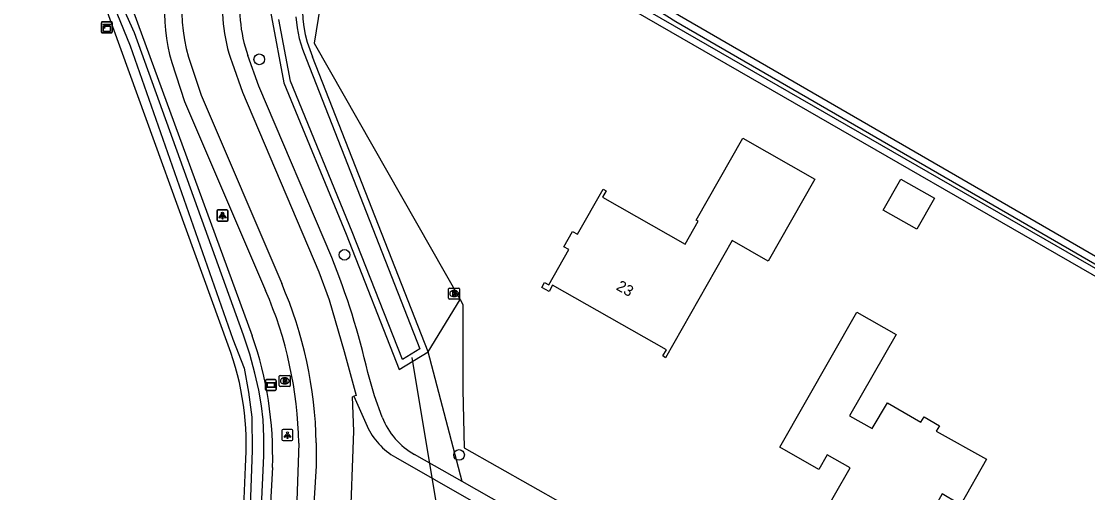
# Model space of a CAD drawing. Extents: x 156502 to 159074, y 384229 to 386094.
# Drawn here: x 157008.2 to 157105.6, y 385784.4 to 385827.5 of the extents above; entities that cross this region are included whole.
import ezdxf

# ---------------------------------------------------------------- set-up
doc = ezdxf.new("R2010")
doc.units = 0
for name, color, linetype in [('IMGEO_Berm_halfverhard', 7, 'Continuous'), ('IMGEO_Boom', 7, 'Continuous'), ('IMGEO_Brandkraan', 7, 'Continuous'), ('IMGEO_Duiker', 7, 'Continuous'), ('IMGEO_Erf', 7, 'Continuous'), ('IMGEO_Groenvoorziening', 7, 'Continuous'), ('IMGEO_Hek', 7, 'Continuous'), ('IMGEO_Kast', 7, 'Continuous'), ('IMGEO_Lichtpunt', 7, 'Continuous'), ('IMGEO_Loofbos', 7, 'Continuous'), ('IMGEO_Pand', 7, 'Continuous'), ('IMGEO_Pand_nummerreeks', 7, 'Continuous'), ('IMGEO_Rijbaan_lokaal_gesloten', 7, 'Continuous'), ('IMGEO_Rijbaan_lokaal_halfverhard', 7, 'Continuous'), ('IMGEO_Rioolput', 7, 'Continuous'), ('IMGEO_Verklikker', 7, 'Continuous'), ('IMGEO_Waterloop', 7, 'Continuous')]:
    doc.layers.add(name, color=color, linetype=linetype)

msp = doc.modelspace()

# ---------------------------------------------------------------- linework, layer by layer
at = {"layer": 'IMGEO_Berm_halfverhard'}
for points in [[(157021.98, 385823.692), (157023.16, 385820.139), (157030.552, 385802.892)], [(157033.583, 385788.947), (157033.399, 385783.694), (157031.512, 385744.51)]]:
    msp.add_lwpolyline(points, dxfattribs=at)
for centre, radius, start, end in [((157039.111, 385828.542), 17.804, 157.16468, 195.80884), ((156996.795, 385788.253), 36.795, 1.08108, 23.44438)]:
    msp.add_arc(centre, radius, start, end, dxfattribs=at)
at = {"layer": 'IMGEO_Boom'}
for centre in [(157029.976, 385823.992), (157037.758, 385806.141), (157048.22, 385787.874)]:
    msp.add_circle(centre, 0.489, dxfattribs=at)
at = {"layer": 'IMGEO_Brandkraan'}
for p, q in [((157031.804, 385794.205), (157031.804, 385795.057)), ((157031.879, 385795.131), (157032.731, 385795.131)), ((157032.292, 385794.911), (157032.317, 385794.911)), ((157032.805, 385795.057), (157032.805, 385794.205)), ((157032.731, 385794.131), (157031.879, 385794.131)), ((157032.315, 385794.351), (157032.29, 385794.351))]:
    msp.add_line(p, q, dxfattribs=at)
for points in [[(157031.804, 385794.205), (157031.804, 385795.057)], [(157031.879, 385795.131), (157032.731, 385795.131)], [(157032.152, 385794.831), (157032.152, 385794.431), (157032.365, 385794.431)], [(157032.383, 385794.831), (157032.152, 385794.831)], [(157032.805, 385795.057), (157032.805, 385794.205)], [(157032.731, 385794.131), (157031.879, 385794.131)], [(157032.331, 385794.75), (157032.277, 385794.75), (157032.277, 385794.674)], [(157032.277, 385794.674), (157032.33, 385794.674)], [(157032.339, 385794.598), (157032.277, 385794.598), (157032.277, 385794.517)], [(157032.277, 385794.517), (157032.339, 385794.517)]]:
    msp.add_lwpolyline(points, dxfattribs=at)
for centre, radius, start, end in [((157031.881, 385795.055), 0.0765, 91.55205, 178.44795), ((157031.881, 385795.055), 0.0765, 91.55205, 178.44795), ((157032.387, 385794.686), 0.145, 59.4692, 91.53667), ((157032.412, 385794.733), 0.0922, 285.51372, 58.15012), ((157032.729, 385795.055), 0.0765, 1.55205, 88.44795), ((157032.729, 385795.055), 0.0765, 1.55205, 88.44795), ((157031.881, 385794.207), 0.0765, 181.55205, 268.44795), ((157031.881, 385794.207), 0.0765, 181.55205, 268.44795), ((157032.332, 385794.712), 0.0379, 267.82845, 90.93552), ((157032.34, 385794.557), 0.0404, 269.87594, 90.50774), ((157032.371, 385794.682), 0.251, 268.66757, 293.53466), ((157032.417, 385794.541), 0.105, 301.31148, 78.98903), ((157032.729, 385794.207), 0.0765, 271.55205, 358.44795), ((157032.729, 385794.207), 0.0765, 271.55205, 358.44795)]:
    msp.add_arc(centre, radius, start, end, dxfattribs=at)
for centre, major_axis, ratio, start_param, end_param in [((157032.291, 385794.631), (-0.387, 0.002), 0.722429, 4.712389, 7.853982), ((157032.316, 385794.631), (-0.39, 0.002), 0.717154, 1.570796, 4.712389)]:
    msp.add_ellipse(centre, major_axis=major_axis, ratio=ratio, start_param=start_param, end_param=end_param, dxfattribs=at)
at = {"layer": 'IMGEO_Duiker'}
msp.add_lwpolyline([(157047.357, 385776.176), (157047.216, 385777.024), (157043.935, 385796.78)], dxfattribs=at)
at = {"layer": 'IMGEO_Erf'}
msp.add_lwpolyline([(157069.688, 385879.771), (157062.244, 385869.451), (157047.224, 385849.55), (157042.786, 385843.67), (157065.314, 385829.887), (157068.346, 385827.983), (157173.435, 385767.228), (157172.677, 385766.006), (157064.372, 385828.327), (157041.356, 385841.775), (157036.588, 385835.458)], dxfattribs=at)
at = {"layer": 'IMGEO_Groenvoorziening'}
for points in [[(157076.448, 385893.546), (157049.627, 385858.357), (157033.907, 385837.957), (157030.83, 385829.194), (157031.084, 385827.859), (157032.23, 385821.835), (157037.896, 385808.02), (157042.738, 385795.688), (157045.399, 385797.293)], [(157015.352, 385835.3), (157016.015, 385834.166), (157020.718, 385833.042), (157020.555, 385832.399), (157020.295, 385831.377), (157019.932, 385829.949), (157017.732, 385830.418), (157029.334, 385798.749)], [(157036.588, 385835.458), (157034.974, 385825.476), (157048.314, 385802.061)], [(157045.399, 385797.293), (157034.848, 385824.224)], [(157045.399, 385797.293), (157048.314, 385802.061)], [(157048.314, 385802.061), (157048.565, 385801.621), (157048.579, 385793.832), (157048.701, 385788.533), (157057.714, 385783.415)], [(157048.506, 385785.444), (157045.399, 385797.293)], [(157031.189, 385786.741), (157030.037, 385766.175), (157029.325, 385750), (157029.3, 385749.437)]]:
    msp.add_lwpolyline(points, dxfattribs=at)
for centre, radius, start, end in [((157044.63, 385828.574), 10.705, 143.35, 203.97313), ((156997.678, 385787.711), 33.525, 358.34127, 19.22204)]:
    msp.add_arc(centre, radius, start, end, dxfattribs=at)
at = {"layer": 'IMGEO_Hek'}
for points in [[(157036.588, 385835.458), (157034.974, 385825.476), (157048.314, 385802.061)], [(157048.314, 385802.061), (157048.565, 385801.621), (157048.579, 385793.832), (157048.701, 385788.533), (157057.714, 385783.415)]]:
    msp.add_lwpolyline(points, dxfattribs=at)
at = {"layer": 'IMGEO_Kast'}
for p, q in [((157015.553, 385826.485), (157015.553, 385827.326)), ((157015.553, 385827.326), (157015.553, 385826.485)), ((157015.628, 385827.41), (157016.469, 385827.41)), ((157016.469, 385827.41), (157015.628, 385827.41)), ((157016.553, 385827.335), (157016.553, 385826.494)), ((157016.553, 385826.494), (157016.553, 385827.335)), ((157016.478, 385826.41), (157015.637, 385826.41)), ((157015.637, 385826.41), (157016.478, 385826.41))]:
    msp.add_line(p, q, dxfattribs=at)
for points in [[(157015.748, 385827.2), (157016.348, 385827.2), (157016.348, 385827.115), (157015.748, 385827.115), (157015.748, 385827.2)], [(157015.748, 385827.025), (157016.348, 385827.025), (157016.348, 385826.536), (157015.748, 385826.536), (157015.748, 385827.025)]]:
    msp.add_lwpolyline(points, dxfattribs=at)
msp.add_circle((157015.832, 385826.874), 0.0377, dxfattribs=at)
for centre, start, end in [((157015.631, 385827.332), 92.4484, 184.28452), ((157015.631, 385827.332), 92.4484, 184.28452), ((157016.475, 385827.332), 2.4484, 94.28452), ((157016.475, 385827.332), 2.4484, 94.28452), ((157015.631, 385826.488), 182.4484, 274.28452), ((157015.631, 385826.488), 182.4484, 274.28452), ((157016.475, 385826.488), 272.4484, 4.28452), ((157016.475, 385826.488), 272.4484, 4.28452)]:
    msp.add_arc(centre, 0.0779, start, end, dxfattribs=at)
at = {"layer": 'IMGEO_Lichtpunt'}
for p, q in [((157026.111, 385810.147), (157026.111, 385809.34)), ((157026.111, 385810.147), (157026.111, 385809.34)), ((157026.126, 385810.12), (157026.126, 385809.313)), ((157026.126, 385810.12), (157026.126, 385809.313)), ((157027.013, 385810.242), (157026.205, 385810.242)), ((157027.013, 385810.242), (157026.205, 385810.242)), ((157027.028, 385810.215), (157026.22, 385810.215)), ((157027.028, 385810.215), (157026.22, 385810.215)), ((157027.107, 385809.34), (157027.107, 385810.147)), ((157027.107, 385809.34), (157027.107, 385810.147)), ((157027.122, 385809.313), (157027.122, 385810.12)), ((157027.122, 385809.313), (157027.122, 385810.12)), ((157026.205, 385809.246), (157027.013, 385809.246)), ((157026.205, 385809.246), (157027.013, 385809.246)), ((157026.22, 385809.219), (157027.028, 385809.219)), ((157026.22, 385809.219), (157027.028, 385809.219)), ((157032.05, 385790.09), (157032.05, 385789.283)), ((157032.05, 385790.09), (157032.05, 385789.283)), ((157032.952, 385790.185), (157032.144, 385790.185)), ((157032.952, 385790.185), (157032.144, 385790.185)), ((157033.046, 385789.283), (157033.046, 385790.09)), ((157033.046, 385789.283), (157033.046, 385790.09)), ((157032.144, 385789.189), (157032.952, 385789.189)), ((157032.144, 385789.189), (157032.952, 385789.189))]:
    msp.add_line(p, q, dxfattribs=at)
for points in [[(157026.485, 385809.811), (157026.524, 385809.783), (157026.336, 385809.521), (157026.298, 385809.548), (157026.485, 385809.811)], [(157026.5, 385809.784), (157026.539, 385809.756), (157026.351, 385809.494), (157026.313, 385809.521), (157026.5, 385809.784)], [(157026.587, 385809.763), (157026.634, 385809.763), (157026.634, 385809.441), (157026.587, 385809.441), (157026.587, 385809.763)], [(157026.602, 385809.736), (157026.649, 385809.736), (157026.649, 385809.414), (157026.602, 385809.414), (157026.602, 385809.736)], [(157026.697, 385809.783), (157026.735, 385809.81), (157026.922, 385809.548), (157026.883, 385809.52), (157026.697, 385809.783)], [(157026.712, 385809.756), (157026.75, 385809.783), (157026.937, 385809.521), (157026.898, 385809.493), (157026.712, 385809.756)], [(157032.424, 385789.754), (157032.463, 385789.726), (157032.275, 385789.464), (157032.237, 385789.491), (157032.424, 385789.754)], [(157032.526, 385789.706), (157032.573, 385789.706), (157032.573, 385789.384), (157032.526, 385789.384), (157032.526, 385789.706)], [(157032.636, 385789.726), (157032.674, 385789.753), (157032.861, 385789.491), (157032.822, 385789.463), (157032.636, 385789.726)]]:
    msp.add_lwpolyline(points, dxfattribs=at)
for centre in [(157026.61, 385809.945), (157026.625, 385809.918), (157032.549, 385789.888)]:
    msp.add_circle(centre, 0.0994, dxfattribs=at)
for centre, start, end in [((157026.205, 385810.147), 90, 180), ((157026.205, 385810.147), 90, 180), ((157026.22, 385810.12), 90, 180), ((157026.22, 385810.12), 90, 180), ((157027.013, 385810.147), 0, 90), ((157027.013, 385810.147), 0, 90), ((157027.028, 385810.12), 0, 90), ((157027.028, 385810.12), 0, 90), ((157026.205, 385809.34), 180, 270), ((157026.205, 385809.34), 180, 270), ((157026.22, 385809.313), 180, 270), ((157026.22, 385809.313), 180, 270), ((157027.013, 385809.34), 270, 0), ((157027.013, 385809.34), 270, 360), ((157027.028, 385809.313), 270, 0), ((157027.028, 385809.313), 270, 360), ((157032.144, 385790.09), 90, 180), ((157032.144, 385790.09), 90, 180), ((157032.952, 385790.09), 0, 90), ((157032.952, 385790.09), 0, 90), ((157032.144, 385789.283), 180, 270), ((157032.144, 385789.283), 180, 270), ((157032.952, 385789.283), 270, 0), ((157032.952, 385789.283), 270, 360)]:
    msp.add_arc(centre, 0.0946, start, end, dxfattribs=at)
at = {"layer": 'IMGEO_Loofbos'}
for points in [[(157027.141, 385797.89), (157015.854, 385829.061), (157010.805, 385836.629), (157000, 385855.161), (156976.182, 385896.012), (156952.047, 385938.123)], [(157027.243, 385749.848), (157027.249, 385750), (157027.878, 385766.343), (157028.705, 385786.777)]]:
    msp.add_lwpolyline(points, dxfattribs=at)
msp.add_arc((157003.007, 385788.827), 25.78, 355.43934, 20.5826, dxfattribs=at)
at = {"layer": 'IMGEO_Pand'}
for points in [[(157067.08, 385796.742), (157066.82, 385796.909), (157067.171, 385797.456), (157056.763, 385803.368), (157056.438, 385802.793), (157055.779, 385803.165), (157056.02, 385803.617), (157056.419, 385803.418), (157058.233, 385806.623), (157057.796, 385806.877), (157058.566, 385808.281), (157059.03, 385808.027), (157061.37, 385812.141), (157061.645, 385811.981), (157061.316, 385811.411), (157068.883, 385807.115), (157070.049, 385809.211), (157069.866, 385809.315), (157074.122, 385816.781), (157080.705, 385813.039), (157076.458, 385805.561), (157073.154, 385807.438), (157067.08, 385796.742)], [(157090.018, 385808.489), (157086.958, 385810.227), (157088.567, 385813.06), (157091.627, 385811.322), (157090.018, 385808.489)], [(157094.034, 385783.344), (157093.774, 385783.484), (157092.329, 385784.314), (157091.181, 385782.261), (157091.819, 385781.904), (157091.56, 385781.44), (157089.098, 385777.114), (157081.073, 385781.715), (157083.929, 385786.699), (157081.847, 385787.885), (157081.084, 385786.547), (157077.502, 385788.588), (157084.548, 385800.906), (157088.147, 385798.874), (157083.885, 385791.439), (157085.956, 385790.275), (157087.339, 385792.644), (157090.403, 385790.86), (157090.692, 385791.357), (157092.087, 385790.545), (157091.801, 385790.041), (157096.381, 385787.475), (157094.034, 385783.344)]]:
    msp.add_lwpolyline(points, dxfattribs=at)
at = {"layer": 'IMGEO_Rijbaan_lokaal_gesloten'}
for points in [[(157023.499, 385824.197), (157024.658, 385820.707), (157032.023, 385803.522)], [(157027.488, 385823.674), (157028.432, 385820.994), (157035.414, 385804.593), (157036.361, 385802.028), (157037.739, 385797.316), (157038.81, 385793.315), (157038.604, 385793.23)], [(157038.321, 385778.978), (157038.272, 385780.907), (157038.618, 385790.04), (157038.48, 385793.19), (157038.604, 385793.23)], [(157038.604, 385793.23), (157039.825, 385790.502)], [(157035.183, 385788.978), (157035.156, 385786.878), (157034.792, 385780.921), (157034.276, 385768.562), (157033.061, 385744.424)], [(157042.417, 385787.656), (157155.604, 385722.866)]]:
    msp.add_lwpolyline(points, dxfattribs=at)
for centre, radius, start, end in [((157039.128, 385828.54), 16.221, 149.95096, 195.52867), ((157041.52, 385828.676), 14.897, 171.39314, 199.61838), ((156996.765, 385788.246), 38.425, 1.09141, 23.42506), ((157045.486, 385793.055), 6.21, 204.27048, 240.38102)]:
    msp.add_arc(centre, radius, start, end, dxfattribs=at)
at = {"layer": 'IMGEO_Rijbaan_lokaal_halfverhard'}
for points in [[(157036.595, 385805.9), (157029.935, 385821.546), (157028.928, 385824.341)], [(157041.212, 385791.315), (157040.509, 385793.275), (157039.878, 385795.397)], [(157048.506, 385785.444), (157044.158, 385787.921)], [(157055.407, 385781.512), (157048.506, 385785.444)]]:
    msp.add_lwpolyline(points, dxfattribs=at)
for centre, radius, start, end in [((157041.034, 385828.611), 12.837, 169.82625, 199.42679), ((156974.097, 385780.6), 67.424, 12.67731, 22.03881), ((157047.365, 385793.68), 6.592, 201.02754, 240.88857)]:
    msp.add_arc(centre, radius, start, end, dxfattribs=at)
at = {"layer": 'IMGEO_Rioolput'}
for p, q in [((157047.271, 385802.178), (157047.271, 385803.03)), ((157047.346, 385803.104), (157048.198, 385803.104)), ((157047.759, 385802.884), (157047.784, 385802.884)), ((157048.272, 385803.03), (157048.272, 385802.178)), ((157048.198, 385802.104), (157047.346, 385802.104)), ((157047.782, 385802.324), (157047.757, 385802.324))]:
    msp.add_line(p, q, dxfattribs=at)
for points in [[(157047.271, 385802.178), (157047.271, 385803.03)], [(157047.346, 385803.104), (157048.198, 385803.104)], [(157047.86, 385802.802), (157047.608, 385802.804), (157047.608, 385802.404)], [(157047.786, 385802.723), (157047.732, 385802.723), (157047.732, 385802.642)], [(157047.732, 385802.642), (157047.784, 385802.642)], [(157048.272, 385803.03), (157048.272, 385802.178)], [(157048.198, 385802.104), (157047.346, 385802.104)], [(157047.608, 385802.404), (157047.732, 385802.404), (157047.732, 385802.566), (157047.743, 385802.566)], [(157047.79, 385802.537), (157047.861, 385802.404), (157048.001, 385802.404), (157047.936, 385802.53)]]:
    msp.add_lwpolyline(points, dxfattribs=at)
for centre, radius, start, end in [((157047.348, 385803.028), 0.0765, 91.55205, 178.44795), ((157047.348, 385803.028), 0.0765, 91.55205, 178.44795), ((157047.768, 385802.831), 0.19, 274.7715, 282.96867), ((157047.792, 385802.627), 0.0964, 77.00612, 93.18647), ((157047.806, 385802.684), 0.0378, 276.66336, 79.67722), ((157047.859, 385802.692), 0.109, 350.36119, 89.41601), ((157047.857, 385802.692), 0.112, 277.58423, 350.98172), ((157047.841, 385802.477), 0.108, 29.51342, 73.79051), ((157048.196, 385803.028), 0.0765, 1.55205, 88.44795), ((157048.196, 385803.028), 0.0765, 1.55205, 88.44795), ((157047.348, 385802.18), 0.0765, 181.55205, 268.44795), ((157047.348, 385802.18), 0.0765, 181.55205, 268.44795), ((157047.742, 385802.513), 0.0533, 26.02933, 88.69889), ((157048.196, 385802.18), 0.0765, 271.55205, 358.44795), ((157048.196, 385802.18), 0.0765, 271.55205, 358.44795)]:
    msp.add_arc(centre, radius, start, end, dxfattribs=at)
for centre, major_axis, ratio, start_param, end_param in [((157047.758, 385802.604), (-0.387, 0.002), 0.722429, 4.712389, 7.853982), ((157047.783, 385802.604), (-0.39, 0.002), 0.717154, 1.570796, 4.712389)]:
    msp.add_ellipse(centre, major_axis=major_axis, ratio=ratio, start_param=start_param, end_param=end_param, dxfattribs=at)
at = {"layer": 'IMGEO_Verklikker'}
for p, q in [((157030.538, 385793.848), (157030.538, 385794.648)), ((157030.538, 385794.648), (157030.538, 385793.848)), ((157030.638, 385794.748), (157031.428, 385794.748)), ((157031.428, 385794.748), (157030.638, 385794.748)), ((157031.528, 385794.648), (157031.528, 385793.848)), ((157031.528, 385793.848), (157031.528, 385794.648)), ((157031.428, 385793.748), (157030.638, 385793.748)), ((157030.638, 385793.748), (157031.428, 385793.748))]:
    msp.add_line(p, q, dxfattribs=at)
for points in [[(157030.639, 385794.48), (157031.427, 385794.48), (157031.427, 385794.016), (157030.639, 385794.016), (157030.639, 385794.48)], [(157030.704, 385794.415), (157030.704, 385794.081), (157031.362, 385794.081), (157031.362, 385794.415), (157030.704, 385794.415)]]:
    msp.add_lwpolyline(points, dxfattribs=at)
for centre, start, end in [((157030.638, 385794.648), 90, 180), ((157030.638, 385794.648), 90, 180), ((157030.638, 385793.848), 180, 270), ((157030.638, 385793.848), 180, 270), ((157031.428, 385794.648), 0, 90), ((157031.428, 385794.648), 360, 90), ((157031.428, 385793.848), 270, 0), ((157031.428, 385793.848), 270, 0)]:
    msp.add_arc(centre, 0.1, start, end, dxfattribs=at)
at = {"layer": 'IMGEO_Waterloop'}
for points in [[(156951.435, 385939.137), (156952.022, 385939.384), (156952.452, 385938.78), (156975.353, 385899.502), (156981.399, 385889.178), (156992.799, 385869.326), (157014.016, 385832.518), (157014.887, 385831.813), (157016.071, 385830.387), (157018.182, 385825.214), (157027.558, 385798.454), (157028.583, 385795.802), (157028.993, 385793.594), (157029.286, 385791.31), (157029.321, 385788.288), (157028.581, 385767.902), (157027.471, 385744.333), (157025.899, 385729.166)], [(157026.893, 385728.82), (157027.719, 385737.195), (157028.276, 385742.87), (157028.936, 385751.506), (157029.301, 385764.209), (157030.134, 385782.51), (157030.404, 385787.798), (157030.382, 385789.519), (157030.333, 385791.081), (157030.183, 385792.361), (157029.921, 385793.785), (157029.576, 385795.332), (157029.12, 385797.085), (157028.52, 385798.817), (157018.567, 385826.419), (157016.741, 385830.496)], [(157064.986, 385829.358), (157068.025, 385827.45), (157172.568, 385767.011), (157172.466, 385766.846), (157064.684, 385828.865)], [(157033.325, 385827.86), (157033.432, 385826.863), (157033.627, 385825.88), (157033.909, 385824.918), (157034.274, 385823.984), (157044.628, 385797.555), (157043.048, 385796.601), (157038.473, 385808.252), (157032.829, 385822.013), (157031.759, 385827.64)]]:
    msp.add_lwpolyline(points, dxfattribs=at)

# ---------------------------------------------------------------- texts
at = {"layer": 'IMGEO_Pand_nummerreeks'}
msp.add_text('23', height=1, rotation=330.40197, dxfattribs=at).set_placement((157062.496, 385803.01))

doc.saveas('drawing.dxf')
